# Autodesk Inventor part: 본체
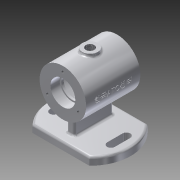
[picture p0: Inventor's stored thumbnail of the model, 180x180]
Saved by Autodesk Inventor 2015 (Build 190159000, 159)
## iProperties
Created: 2021-09
Part Number: 본체
Material: 알루미늄 6061
Document SubType Name: Modeling
Designer: now
Density: 2.7 g/cm^3
Appearance: 알루미늄 - 평지
Mass: 473.3 g
Surface Area: 491.222 cm^2
Volume: 175.296 cm^3
Author: now
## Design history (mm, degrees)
sketch "스케치1"
  geometry: C1 r 52.5 at (0, 0); 1 further point
  constraints: 1 centre point, 1 coincident
  dimensions: "d0" = 105 diameter of C1
extrude "돌출1" new body sketch "스케치1" distance "d1" = 10; taper "d2" = 0 deg
sketch "스케치2"
  geometry: L1 (-50.501, -57.168)-(50.091, -57.168); L2 (50.091, -57.168)-(50.091, -37.5); L3 (50.091, -37.5)-(-50.501, -37.5); L4 (-50.501, -37.5)-(-50.501, -57.168); L5 (-52.55, 37.5)-(54.394, 37.5); L6 (54.394, 37.5)-(54.394, 61.88); L7 (54.394, 61.88)-(-52.55, 61.88); L8 (-52.55, 61.88)-(-52.55, 37.5); C1 r 52.5 at (0, 0) reference
  constraints: 16 end point, 4 parallel, 2 horizontal, 2 perpendicular
  dimensions: "d3" = 37.5 distance from line of C1.centre L3; "d4" = 37.5 distance from line of L5 C1.centre
extrude "돌출2" cut sketch "스케치2" stored distance "d5" = 10; taper "d6" = 0 deg
sketch "스케치3"
  geometry: L1 (-37.5, 0)-(-37.5, 10) reference; L2 (-37.5, 10)-(37.5, 10) reference; L3 (37.5, 10)-(37.5, 0) reference; L4 (37.5, 0)-(-37.5, 0) reference; L5 (-35, 92)-(35, 92); L6 (35, 92)-(35, 62); L7 (35, 62)-(-35, 62); L8 (-35, 62)-(-35, 92); 1 further point
  constraints: 8 end point, 2 parallel, 1 horizontal, 1 perpendicular
  dimensions: "d7" = 62 distance between parallel lines of L4 L7; "d8" = 35 distance from line of L8 point (0, 0); "d9" = 60 diameter of L5 L7; "d76" = 70 distance of L5.start L5.end
revolve "회전1" sketch "스케치3" stored, may be unused: angle "d10" = 90 deg
sketch "스케치5"
  geometry: L1 (5, 25)-(-5, 25); L2 (-5, 25)-(-5, -25); L3 (-5, -25)-(5, -25); L4 (5, -25)-(5, 25); L5 (5, 25)-(-5, -25); L6 (-5, 25)-(5, -25); A1 r 52.5 centre (0, 0) between (36.742, -37.5) and (36.742, 37.5) reference
  constraints: 12 end point, 2 midpoint, 2 parallel, 1 horizontal, 1 perpendicular
  dimensions: "d11" = 50 distance of L1.end L2.end; "d12" = 10 distance of L1.start L1.end
extrude "돌출3" join sketch "스케치5" stored distance "d13" = 10; taper "d14" = 0 deg
sketch "스케치7"
  geometry: L1 (36.742, 37.5)-(-36.742, 37.5) reference; L2 (-36.742, -37.5)-(36.742, -37.5) reference; L3 (37, 10)-(37, -10); L4 (32, 10)-(32, -10); L5 (42, -10)-(42, 10); L6 (0, -37.5)-(0, 37.5); L7 (-32, 10)-(-32, -10); L8 (-42, -10)-(-42, 10); A1 r 52.5 centre (0, 0) between (-36.742, 37.5) and (-36.742, -37.5) reference; A2 r 5 centre (37, 10) between (42, 10) and (32, 10); A3 r 5 centre (37, -10) between (32, -10) and (42, -10); A4 r 5 centre (-37, 10) between (-32, 10) and (-42, 10); A5 r 5 centre (-37, -10) between (-42, -10) and (-32, -10); 1 further point
  constraints: 14 end point, 8 point on circle, 6 symmetric about line, 4 centre point, 4 tangent, 3 midpoint, 1 parallel, 1 vertical, 2 other
  dimensions: "d15" = 20 distance of L3.start L3.end; "d16" = 37 distance of point (37, 0) A1.centre; "d87" = 10 distance between parallel lines of L5 L4
extrude "돌출4" cut sketch "스케치7" stored distance "d17" = 10; taper "d18" = 0 deg
sketch "스케치8"
  geometry: C1 r 30 at (0, 0) reference; 1 further point
hole "구멍1" sketch "스케치8" at (0, 0) diameter "d19" = 32; stored, may be unused: countersink angle "d23" = 90 deg, drill point angle "d25" = 0 deg; dims "d20" = 6, "d21" = 32, "d22" = 12, "d24" = 12
sketch "스케치9"
  geometry: C1 r 16 at (0, 0) reference; 1 further point
hole "구멍2" sketch "스케치9" at (0, 0) diameter "d26" = 28; stored, may be unused: countersink angle "d30" = 90 deg, drill point angle "d32" = 0 deg; dims "d27" = 6, "d28" = 32, "d29" = 12, "d31" = 3
sketch "스케치10"
  geometry: C1 r 14 at (0, 0) reference; 1 further point
hole "구멍3" sketch "스케치10" at (0, 0) diameter "d33" = 50; stored, may be unused: countersink angle "d37" = 90 deg, drill point angle "d39" = 0 deg; dims "d34" = 6, "d35" = 32, "d36" = 12, "d38" = 40
sketch "스케치11"
  geometry: C1 r 30 at (0, 0) reference; 1 further point
hole "구멍4" sketch "스케치11" at (0, 0) diameter "d40" = 32; stored, may be unused: countersink angle "d44" = 90 deg, drill point angle "d46" = 0 deg; dims "d41" = 6, "d42" = 32, "d43" = 12, "d45" = 12
sketch "스케치12"
  geometry: C1 r 16 at (0, 0) reference; 1 further point
hole "구멍5" sketch "스케치12" at (0, 0) diameter "d47" = 28; stored, may be unused: countersink angle "d51" = 90 deg, drill point angle "d53" = 0 deg; dims "d48" = 6, "d49" = 32, "d50" = 12, "d52" = 3
node "작업 평면1"
sketch "스케치13"
  geometry: L1 (-30, -35)-(-30, 35) reference; L2 (30, -35)-(-30, -35) reference; L3 (30, 35)-(-30, 35) reference; L4 (30, -35)-(30, 35) reference; C1 r 10 at (0, 0); 1 further point
  constraints: 1 centre point, 1 coincident
  dimensions: "d55" = 20 diameter of C1
extrude "돌출5" join sketch "스케치13" stored distance "d56" = 10; taper "d57" = 0 deg
sketch "스케치14"
  geometry: C1 r 10 at (0, 0) reference
hole "구멍6" sketch "스케치14" at (0, 0) diameter "d58" = 10.917; stored, may be unused: countersink angle "d62" = 90 deg, drill point angle "d64" = 118 deg; dims "d59" = 24, "d60" = 32, "d61" = 12, "d63" = 29.1
sketch "스케치15"
  geometry: C1 r 16 at (0, 0) reference; 2 further points
  constraints: 1 vertical alignment
  dimensions: "d65" = 23 distance of C1.centre point (0, 23)
hole "구멍7" sketch "스케치15" at (0, 23) diameter "d66" = 3.242; stored, may be unused: countersink angle "d70" = 90 deg, drill point angle "d72" = 118 deg; dims "d67" = 8, "d68" = 32, "d69" = 12, "d71" = 10
fillet "모깎기1" dims "d77" = 0.3
fillet "모깎기2" dims "d78" = 3
fillet "모깎기3" dims "d79" = 3
fillet "모깎기4" dims "d80" = 3
fillet "모깎기5" dims "d81" = 3
node "작업 평면3"
sketch "스케치16"
  geometry: L1 (-35, 32)-(-35, 92) reference; L2 (-35, 92)-(35, 92) reference; L3 (-35, 32)-(35, 32) reference; L4 (35, 32)-(35, 92) reference; L5 (-37.5, 0)-(37.5, 0) reference; 3 further points
  constraints: 1 midpoint, 1 vertical alignment, 1 other
  dimensions: "d83" = 30 distance from line of point (0, 62) L2
feature "엠보싱1" sketch "스케치16" dims "d7" = 62, "d8" = 35, "d9" = 60, "d76" = 70, "d84" = 0.5, "d85" = 0
fillet "모깎기6" dims "d86" = 3
node "솔리드1"
pattern_circular "원형 패턴1" dims angle "d74" = 360 deg
mirror "대칭2"
node "절단 모서리 투영1"
other parameters: "d54" = 95
